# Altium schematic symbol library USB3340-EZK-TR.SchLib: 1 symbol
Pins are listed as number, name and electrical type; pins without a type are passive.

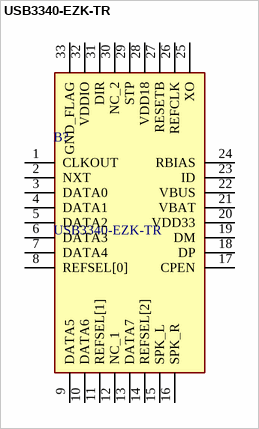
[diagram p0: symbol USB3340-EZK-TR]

## USB3340-EZK-TR
designator B?
Microchip USB3340-EZK-TR, USB Transceiver, USB 2.0 at 480Mbit/s, 5.5 V, 32-Pin QFN; Geometry.Height: 1mm
footprint QFN50P500X500X100-33N-D
pins: 1 CLKOUT, 2 NXT, 3 DATA0, 4 DATA1, 5 DATA2, 6 DATA3, 7 DATA4, 8 REFSEL[0], 9 DATA5, 10 DATA6, 11 REFSEL[1], 12 NC_1, 13 DATA7, 14 REFSEL[2], 15 SPK_L, 16 SPK_R, 17 CPEN, 18 DP, 19 DM, 20 VDD33, 21 VBAT, 22 VBUS, 23 ID, 24 RBIAS, 25 XO, 26 REFCLK, 27 RESETB, 28 VDD18, 29 STP, 30 NC_2, 31 DIR, 32 VDDIO, 33 GND_FLAG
